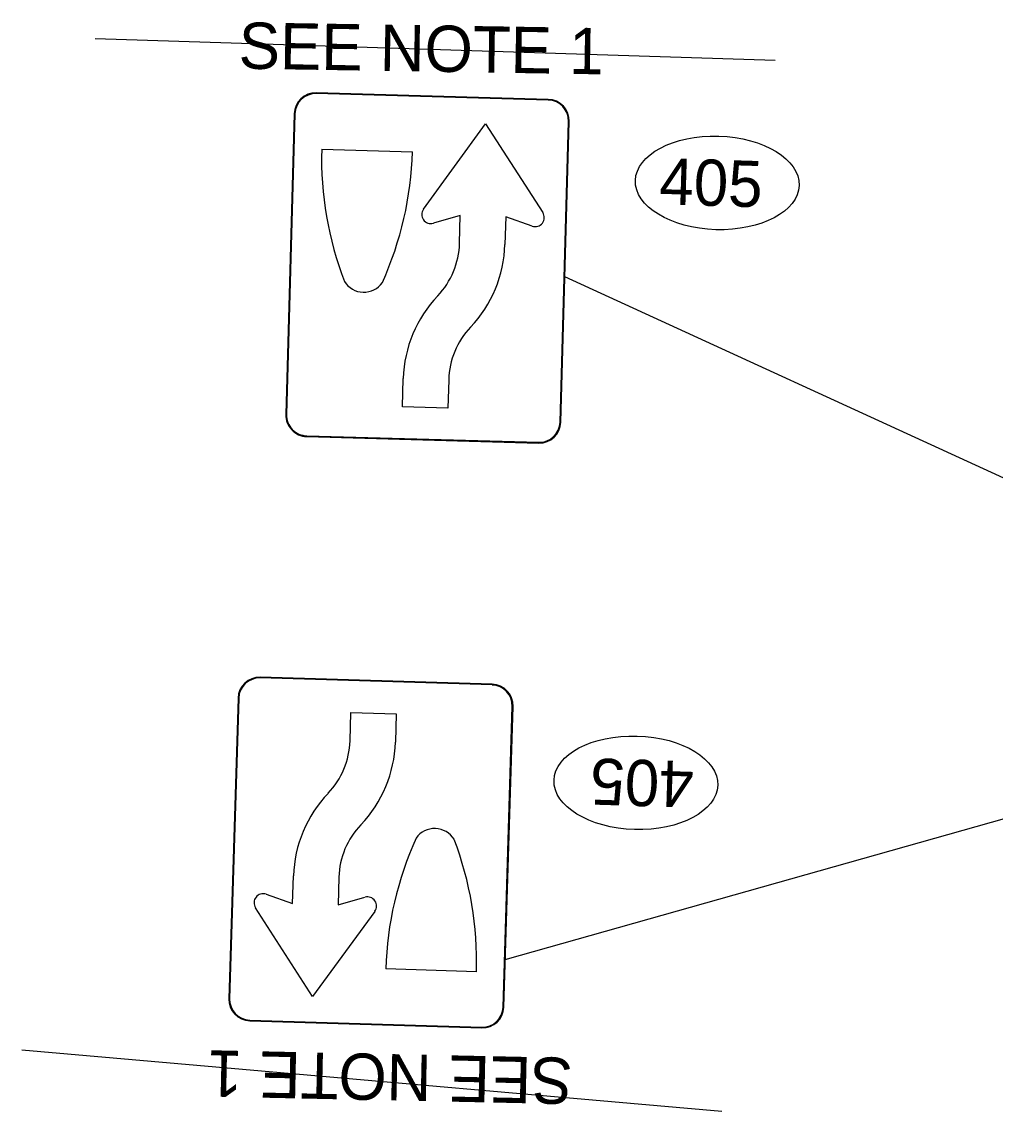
# Model space of a CAD drawing. Extents: x 2096670 to 2098561, y 684033 to 689893.
# Drawn here: x 2097447.9 to 2097700.1, y 687939.4 to 688221.7 of the extents above; entities that cross this region are included whole.
import ezdxf

# ---------------------------------------------------------------- set-up
doc = ezdxf.new("R2010")
doc.units = 0
for name, color, linetype in [('Exist Sign E Stop CELL', 7, 'Continuous'), ('Prop DSN Text', 7, 'Continuous'), ('Prop Sign E Keep Right CELL', 7, 'Continuous'), ('Prop Sign E One Way_Right CELL', 7, 'Continuous'), ('Scratch_Level_3', 7, 'Continuous')]:
    doc.layers.add(name, color=color, linetype=linetype)

# ---------------------------------------------------------------- blocks, each defined once
blk = doc.blocks.new('R4_7A')
at = {"layer": 'Prop Sign E Keep Right CELL'}
blk.add_line((0.563, 6.375), (2.563, 6.375), dxfattribs=at)
blk.add_line((0.563, 6.375), (2.563, 6.375), dxfattribs=at)
blk.add_line((0.563, 6.375), (2.563, 6.375), dxfattribs=at)
for points in [[(2.841, 5.115), (4.156, 7.031), (5.471, 5.115)], [(2.841, 5.115), (4.156, 7.031), (5.471, 5.115)], [(2.841, 5.115), (4.156, 7.031), (5.471, 5.115)], [(3.656, 4.387), (3.656, 4.998), (3.067, 4.811)], [(3.656, 4.387), (3.656, 4.998), (3.067, 4.811)], [(3.656, 4.387), (3.656, 4.998), (3.067, 4.811)], [(5.246, 4.811), (4.656, 4.998), (4.656, 4.387)], [(5.246, 4.811), (4.656, 4.998), (4.656, 4.387)], [(5.246, 4.811), (4.656, 4.998), (4.656, 4.387)], [(3.5, 1.375), (3.5, 0.75), (2.5, 0.75), (2.5, 1.375)], [(3.5, 1.375), (3.5, 0.75), (2.5, 0.75), (2.5, 1.375)], [(3.5, 1.375), (3.5, 0.75), (2.5, 0.75), (2.5, 1.375)]]:
    blk.add_lwpolyline(points, dxfattribs=at)
for centre, radius, start, end in [((8.062, 6.373), 7.5, 179.9823, 202.7267), ((8.062, 6.373), 7.5, 179.9823, 202.7267), ((8.062, 6.373), 7.5, 179.9823, 202.7267), ((-4.938, 6.373), 7.5, 337.2733, 0.0177), ((-4.938, 6.373), 7.5, 337.2733, 0.0177), ((-4.938, 6.373), 7.5, 337.2733, 0.0177), ((3.006, 5.001), 0.2, 145.5508, 287.601), ((3.006, 5.001), 0.2, 145.5508, 287.601), ((3.006, 5.001), 0.2, 145.5508, 287.601), ((5.306, 5.001), 0.2, 252.399, 34.4492), ((5.306, 5.001), 0.2, 252.399, 34.4492), ((5.306, 5.001), 0.2, 252.399, 34.4492), ((1.906, 4.387), 1.75, 317.9924, 0), ((1.906, 4.387), 1.75, 317.9924, 0), ((1.906, 4.387), 1.75, 317.9924, 0), ((1.906, 4.387), 2.75, 317.9924, 0), ((1.906, 4.387), 2.75, 317.9924, 0), ((1.906, 4.387), 2.75, 317.9924, 0), ((1.562, 3.75), 0.5, 213.3458, 326.6542), ((1.562, 3.75), 0.5, 213.3458, 326.6542), ((1.562, 3.75), 0.5, 213.3458, 326.6542), ((5.25, 1.375), 2.75, 137.9924, 180), ((5.25, 1.375), 2.75, 137.9924, 180), ((5.25, 1.375), 2.75, 137.9924, 180), ((5.25, 1.375), 1.75, 137.9924, 180), ((5.25, 1.375), 1.75, 137.9924, 180), ((5.25, 1.375), 1.75, 137.9924, 180)]:
    blk.add_arc(centre, radius, start, end, dxfattribs=at)

msp = doc.modelspace()

# ---------------------------------------------------------------- linework, layer by layer
at = {"layer": 'Exist Sign E Stop CELL'}
msp.add_line((2097766.18, 688074.08), (2097588.59, 688155.57), dxfattribs=at)
at = {"layer": 'Prop Sign E Keep Right CELL'}
for p, q in [((2097584.3, 688201.6), (2097524.19, 688203.27)), ((2097584.3, 688201.41), (2097524.19, 688203.09)), ((2097518.47, 688197.86), (2097516.31, 688119.94)), ((2097518.66, 688197.86), (2097516.49, 688119.94)), ((2097587.36, 688117.96), (2097589.53, 688195.88)), ((2097587.55, 688117.96), (2097589.72, 688195.88)), ((2097521.72, 688114.22), (2097521.72, 688114.4)), ((2097521.72, 688114.4), (2097581.83, 688112.73)), ((2097521.72, 688114.22), (2097521.72, 688114.4)), ((2097521.72, 688114.22), (2097581.83, 688112.55)), ((2097569.76, 688049.85), (2097509.65, 688051.68)), ((2097569.76, 688050.03), (2097509.66, 688051.86)), ((2097569.76, 688050.03), (2097569.76, 688049.85)), ((2097569.76, 688050.03), (2097569.76, 688049.85)), ((2097503.92, 688046.46), (2097501.55, 687968.55)), ((2097504.11, 688046.46), (2097501.74, 687968.54)), ((2097572.61, 687966.39), (2097574.97, 688044.3)), ((2097572.79, 687966.38), (2097575.16, 688044.3)), ((2097506.95, 687962.81), (2097567.05, 687960.99)), ((2097506.96, 687963), (2097567.06, 687961.17))]:
    msp.add_line(p, q, dxfattribs=at)
for centre, radius, start, end in [((2097524.04, 688197.71), 5.57, 88.4071, 178.4071), ((2097524.04, 688197.71), 5.38, 88.4071, 178.4071), ((2097584.15, 688196.03), 5.38, 358.4071, 88.4071), ((2097584.15, 688196.03), 5.57, 358.4071, 88.4071), ((2097521.88, 688119.79), 5.57, 178.4071, 268.4071), ((2097521.88, 688119.79), 5.38, 178.4071, 268.4071), ((2097581.99, 688118.11), 5.57, 268.4071, 358.4071), ((2097581.99, 688118.11), 5.38, 268.4071, 358.4071), ((2097509.49, 688046.29), 5.57, 88.2587, 178.2587), ((2097509.49, 688046.29), 5.38, 88.2587, 178.2587), ((2097569.59, 688044.47), 5.38, 358.2587, 88.2587), ((2097569.59, 688044.47), 5.57, 358.2587, 88.2587), ((2097507.12, 687968.38), 5.57, 178.2587, 268.2587), ((2097507.12, 687968.38), 5.38, 178.2587, 268.2587), ((2097567.22, 687966.55), 5.57, 268.2587, 358.2587), ((2097567.22, 687966.55), 5.38, 268.2587, 358.2587)]:
    msp.add_arc(centre, radius, start, end, dxfattribs=at)
at = {"layer": 'Prop Sign E One Way_Right CELL'}
msp.add_line((2097573.16, 687978.74), (2097759.04, 688031.27), dxfattribs=at)
for centre, major_axis in [((2097628.07, 688179.95), (-21.21, 0.64)), ((2097606.99, 688024.51), (21.21, -0.64))]:
    msp.add_ellipse(centre, major_axis=major_axis, ratio=0.571429, dxfattribs=at)
at = {"layer": 'Scratch_Level_3'}
for p, q in [((2097466.94, 688217.36), (2097643.08, 688211.73)), ((2097447.9, 687955.35), (2097629.26, 687939.41))]:
    msp.add_line(p, q, dxfattribs=at)

# ---------------------------------------------------------------- block references
at = {"layer": 'Prop Sign E Keep Right CELL', "xscale": 11.75936655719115}
for p, yscale, rotation in [((2097516.9, 688113.94), 11.759366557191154, -1.5928674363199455), ((2097574.58, 688050.3), 11.759366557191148, 178.25868552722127)]:
    msp.add_blockref('R4_7A', p, dxfattribs=dict(at, yscale=yscale, rotation=rotation))

# ---------------------------------------------------------------- texts
at = {"layer": 'Prop DSN Text'}
for rotation, p in [(359.0865, (2097504.02, 688209.57)), (178.7898, (2097590.7, 687953.22))]:
    msp.add_text('SEE NOTE 1', height=12, rotation=rotation, dxfattribs=at).set_placement(p)
at = {"layer": 'Prop Sign E One Way_Right CELL'}
for rotation, p in [(358.2587, (2097612.93, 688174.42)), (178.2587, (2097622.13, 688030.04))]:
    msp.add_text('405', height=11.98, rotation=rotation, dxfattribs=at).set_placement(p)

doc.saveas('drawing.dxf')
